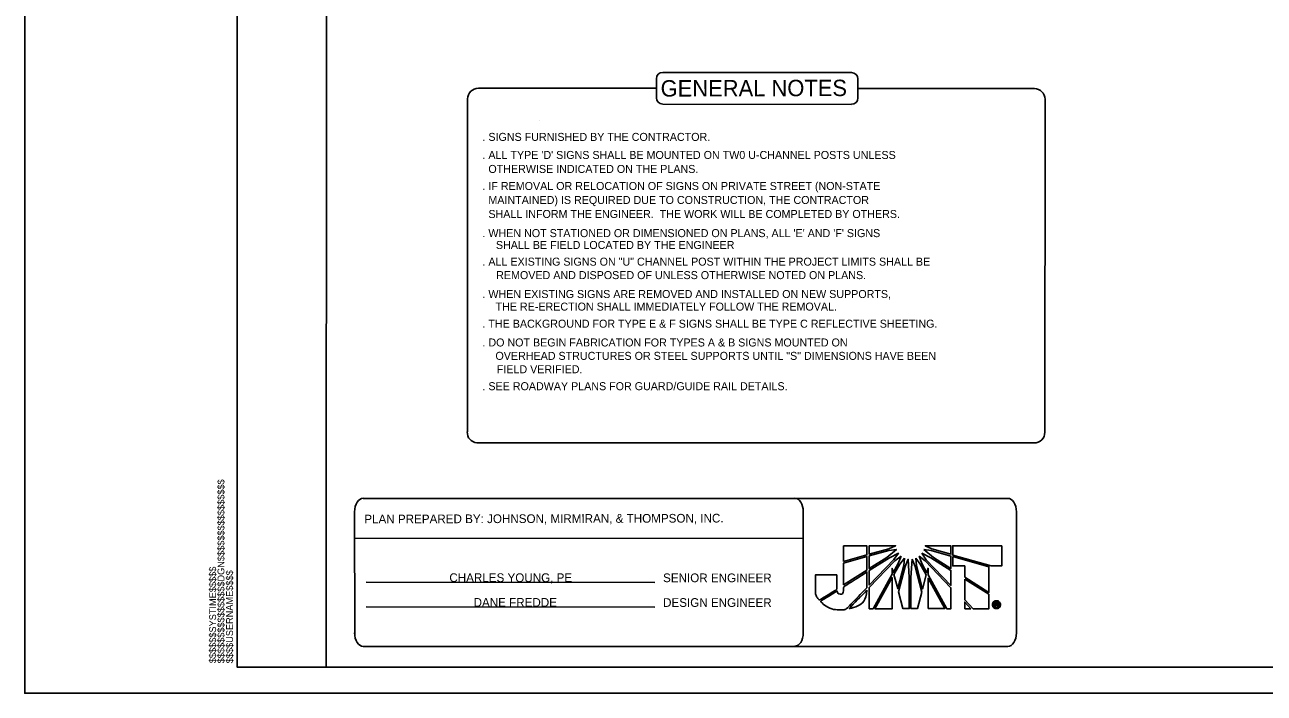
# Model space of a CAD drawing. Extents: x 49201 to 52602, y 49383 to 50479.
# Drawn here: x 50703 to 51649, y 49383 to 49894 of the extents above; entities that cross this region are included whole.
import ezdxf

# ---------------------------------------------------------------- set-up
doc = ezdxf.new("R2010")
doc.units = 0
for name, color, linetype in [('Default', 7, 'Continuous'), ('Old_Level_18', 7, 'Continuous'), ('Old_Level_41', 7, 'Continuous'), ('Old_Level_50', 7, 'Continuous'), ('Sheet Plot Border Outside CELL', 7, 'Continuous'), ('Sheet Title CELL', 7, 'Continuous')]:
    doc.layers.add(name, color=color, linetype=linetype)

msp = doc.modelspace()

# ---------------------------------------------------------------- linework, layer by layer
at = {"layer": 'Default'}
for p, q in [((51095.68, 49820.52), (51095.68, 49820.52)), ((51095.68, 49820.52), (51095.68, 49820.52)), ((50961.32, 49532.17), (51453.54, 49532.17)), ((50954.93, 49428.53), (50954.91, 49521.98)), ((51297.31, 49522.91), (51297.32, 49429.46)), ((51459.95, 49521.93), (51459.95, 49429.37)), ((50954.9, 49501.56), (51297.33, 49501.67)), ((51345.87, 49495.84), (51328.11, 49495.84)), ((51328.11, 49495.84), (51328.11, 49484.05)), ((51345.87, 49488.98), (51345.87, 49495.84)), ((51367.72, 49495.93), (51347.72, 49495.93)), ((51347.72, 49495.93), (51347.72, 49489.56)), ((51362.62, 49493.67), (51367.72, 49495.93)), ((51410.06, 49495.84), (51390.36, 49495.93)), ((51390.36, 49495.93), (51395.34, 49493.58)), ((51410.06, 49489.45), (51410.06, 49495.84)), ((51448.8, 49495.93), (51411.44, 49495.93)), ((51411.44, 49495.93), (51411.44, 49489.07)), ((51448.8, 49480.62), (51448.8, 49495.93)), ((51328.11, 49484.05), (51345.87, 49488.98)), ((51345.87, 49487.69), (51328.11, 49482.7)), ((51345.87, 49477.4), (51345.87, 49487.69)), ((51347.72, 49489.56), (51362.62, 49493.67)), ((51362.62, 49492.29), (51347.72, 49488.19)), ((51347.72, 49488.19), (51347.72, 49478.57)), ((51347.72, 49478.57), (51361.06, 49487.01)), ((51363.12, 49486.81), (51347.72, 49477.01)), ((51361.06, 49487.01), (51368.42, 49493)), ((51368.42, 49493), (51362.62, 49492.29)), ((51369.89, 49490.24), (51363.12, 49486.81)), ((51366.46, 49485.43), (51369.89, 49490.24)), ((51371.94, 49488.1), (51367.22, 49484.46)), ((51369.77, 49482.41), (51371.94, 49488.1)), ((51374.49, 49486.52), (51370.98, 49482)), ((51374, 49481.03), (51374.49, 49486.52)), ((51377.43, 49485.72), (51374.99, 49480.03)), ((51378.19, 49471.71), (51377.43, 49485.72)), ((51380.36, 49485.72), (51379.45, 49471.71)), ((51382.7, 49480.03), (51380.36, 49485.72)), ((51383.2, 49486.52), (51383.79, 49480.83)), ((51386.63, 49482), (51383.2, 49486.52)), ((51385.72, 49488.1), (51387.9, 49482.41)), ((51390.45, 49484.46), (51385.72, 49488.1)), ((51387.81, 49490.24), (51391.24, 49485.34)), ((51394.67, 49486.81), (51387.81, 49490.24)), ((51389.36, 49493), (51396.81, 49486.9)), ((51394.84, 49492.29), (51389.36, 49493)), ((51409.95, 49477.1), (51394.67, 49486.81)), ((51410.06, 49488.1), (51394.84, 49492.29)), ((51395.34, 49493.58), (51410.06, 49489.45)), ((51396.81, 49486.9), (51409.95, 49478.69)), ((51409.95, 49478.69), (51410.06, 49488.1)), ((51411.44, 49489.07), (51411.44, 49488.86)), ((51411.44, 49488.86), (51440.85, 49480.62)), ((51411.44, 49487.81), (51411.44, 49487.69)), ((51438.97, 49479.95), (51411.44, 49487.81)), ((51411.44, 49487.69), (51411.44, 49480.53)), ((51328.11, 49482.7), (51328.11, 49466.14)), ((51328.11, 49466.14), (51345.87, 49477.4)), ((51347.72, 49465.93), (51366.46, 49485.43)), ((51367.22, 49484.46), (51347.72, 49464.05)), ((51347.72, 49477.01), (51347.72, 49465.93)), ((51365.17, 49474.17), (51365.17, 49478.86)), ((51365.17, 49478.86), (51366.05, 49475.64)), ((51366.05, 49475.64), (51369.77, 49482.41)), ((51370.98, 49482), (51366.55, 49473.97)), ((51369.39, 49463.29), (51374, 49481.03)), ((51374.99, 49480.03), (51369.98, 49460.83)), ((51387.81, 49460.54), (51382.7, 49480.03)), ((51383.79, 49480.83), (51388.39, 49462.88)), ((51391.24, 49473.67), (51386.63, 49482)), ((51387.9, 49482.41), (51391.71, 49475.34)), ((51409.95, 49463.88), (51390.45, 49484.46)), ((51391.24, 49485.34), (51409.95, 49465.73)), ((51391.71, 49475.34), (51392.62, 49478.86)), ((51392.62, 49478.86), (51392.62, 49473.67)), ((51409.95, 49465.73), (51409.95, 49477.1)), ((51411.44, 49480.53), (51420.56, 49480.53)), ((51420.56, 49480.53), (51420.56, 49472)), ((51438.98, 49460.33), (51438.97, 49479.95)), ((51440.85, 49480.62), (51448.8, 49480.62)), ((50963.67, 49468.1), (51183.98, 49467.98)), ((51350.66, 49447.93), (51365.17, 49474.17)), ((51365.17, 49471.62), (51352.03, 49447.93)), ((51365.29, 49447.93), (51365.17, 49471.62)), ((51366.55, 49473.97), (51369.39, 49463.29)), ((51378.19, 49448.01), (51378.19, 49471.71)), ((51379.45, 49471.71), (51379.45, 49448.01)), ((51388.39, 49462.88), (51391.24, 49473.67)), ((51392.62, 49473.67), (51406.81, 49447.93)), ((51405.34, 49448.01), (51392.62, 49471.12)), ((51392.62, 49471.12), (51392.62, 49448.01)), ((51420.56, 49472), (51438.98, 49460.33)), ((51420.56, 49470.53), (51420.56, 49454.64)), ((51438.98, 49458.95), (51420.56, 49470.53)), ((51347.72, 49464.05), (51347.72, 49447.93)), ((51369.98, 49460.83), (51373.32, 49448.01)), ((51384.38, 49448.01), (51387.81, 49460.54)), ((51409.95, 49447.93), (51409.95, 49463.88)), ((51438.98, 49447.93), (51438.98, 49458.95)), ((50963.66, 49449.23), (51183.97, 49449.09)), ((51347.72, 49447.93), (51350.66, 49447.93)), ((51352.03, 49447.93), (51365.29, 49447.93)), ((51373.32, 49448.01), (51378.19, 49448.01)), ((51379.45, 49448.01), (51384.38, 49448.01)), ((51392.62, 49448.01), (51405.34, 49448.01)), ((51406.81, 49447.93), (51409.95, 49447.93)), ((51420.56, 49454.64), (51426.92, 49447.93)), ((51425.16, 49447.93), (51420.56, 49452.91)), ((51420.56, 49452.91), (51420.56, 49447.93)), ((51420.56, 49447.93), (51425.16, 49447.93)), ((51426.92, 49447.93), (51438.98, 49447.93)), ((51443.65, 49449.6), (51443.65, 49452.32)), ((51443.65, 49452.32), (51444.77, 49452.32)), ((51444.27, 49449.6), (51443.65, 49449.6)), ((51444.77, 49451.8), (51444.27, 49451.8)), ((51444.27, 49451.8), (51444.27, 49451.16)), ((51444.27, 49451.16), (51444.77, 49451.16)), ((51444.77, 49450.67), (51444.27, 49450.67)), ((51444.27, 49450.67), (51444.27, 49449.6)), ((51444.77, 49453.93), (51444.77, 49453.36)), ((51444.77, 49453.36), (51444.77, 49453.93)), ((51444.77, 49452.32), (51444.77, 49451.8)), ((51444.77, 49451.8), (51444.77, 49452.32)), ((51444.77, 49452.32), (51444.94, 49452.32)), ((51444.84, 49451.8), (51444.77, 49451.8)), ((51444.77, 49451.16), (51444.77, 49450.67)), ((51444.77, 49450.67), (51444.77, 49451.16)), ((51444.77, 49451.16), (51444.79, 49451.16)), ((51444.79, 49450.67), (51444.77, 49450.67)), ((51444.77, 49448.54), (51444.77, 49447.95)), ((51444.77, 49447.95), (51444.77, 49448.54)), ((51444.77, 49448.54), (51444.79, 49448.54)), ((51444.79, 49447.95), (51444.77, 49447.95)), ((51453.53, 49419.13), (50961.32, 49419.12))]:
    msp.add_line(p, q, dxfattribs=at)
for points in [[(51328.11, 49484.05), (51345.87, 49488.98), (51345.87, 49495.84), (51328.11, 49495.84), (51328.11, 49484.05)], [(51362.62, 49493.67), (51367.72, 49495.93), (51347.72, 49495.93), (51347.72, 49489.56), (51362.62, 49493.67)], [(51395.34, 49493.58), (51410.06, 49489.45), (51410.06, 49495.84), (51390.36, 49495.93), (51395.34, 49493.58)], [(51448.8, 49495.93), (51411.44, 49495.93), (51411.44, 49489.07), (51411.44, 49488.86), (51440.85, 49480.62), (51448.8, 49480.62), (51448.8, 49495.93)], [(51328.11, 49466.14), (51345.87, 49477.4), (51345.87, 49487.69), (51328.11, 49482.7), (51328.11, 49466.14)], [(51347.72, 49488.19), (51347.72, 49478.57), (51361.06, 49487.01), (51368.42, 49493), (51362.62, 49492.29), (51347.72, 49488.19)], [(51347.72, 49477.01), (51347.72, 49465.93), (51366.46, 49485.43), (51369.89, 49490.24), (51363.12, 49486.81), (51347.72, 49477.01)], [(51371.94, 49488.1), (51367.22, 49484.46), (51347.72, 49464.05), (51347.72, 49447.93), (51350.66, 49447.93), (51365.17, 49474.17), (51365.17, 49478.86), (51366.05, 49475.64), (51369.77, 49482.41), (51371.94, 49488.1)], [(51374.49, 49486.52), (51370.98, 49482), (51366.55, 49473.97), (51369.39, 49463.29), (51374, 49481.03), (51374.49, 49486.52)], [(51374.99, 49480.03), (51369.98, 49460.83), (51373.32, 49448.01), (51378.19, 49448.01), (51378.19, 49471.71), (51377.43, 49485.72), (51374.99, 49480.03)], [(51380.36, 49485.72), (51379.45, 49471.71), (51379.45, 49448.01), (51384.38, 49448.01), (51387.81, 49460.54), (51382.7, 49480.03), (51380.36, 49485.72)], [(51383.2, 49486.52), (51383.79, 49480.83), (51388.39, 49462.88), (51391.24, 49473.67), (51386.63, 49482), (51383.2, 49486.52)], [(51385.72, 49488.1), (51387.9, 49482.41), (51391.71, 49475.34), (51392.62, 49478.86), (51392.62, 49473.67), (51406.81, 49447.93), (51409.95, 49447.93), (51409.95, 49463.88), (51390.45, 49484.46), (51385.72, 49488.1)], [(51387.81, 49490.24), (51391.24, 49485.34), (51409.95, 49465.73), (51409.95, 49477.1), (51394.67, 49486.81), (51387.81, 49490.24)], [(51389.36, 49493), (51396.81, 49486.9), (51409.95, 49478.69), (51410.06, 49488.1), (51394.84, 49492.29), (51389.36, 49493)], [(51411.44, 49487.81), (51411.44, 49487.69), (51411.44, 49480.53), (51420.56, 49480.53), (51420.56, 49472), (51438.98, 49460.33), (51438.97, 49479.95), (51411.44, 49487.81)], [(51352.03, 49447.93), (51365.29, 49447.93), (51365.17, 49471.62), (51352.03, 49447.93)], [(51392.62, 49448.01), (51405.34, 49448.01), (51392.62, 49471.12), (51392.62, 49448.01)], [(51420.56, 49470.53), (51420.56, 49454.64), (51426.92, 49447.93), (51438.98, 49447.93), (51438.98, 49458.95), (51420.56, 49470.53), (51420.56, 49470.53)], [(51420.56, 49447.93), (51420.56, 49447.93), (51425.16, 49447.93), (51420.56, 49452.91), (51420.56, 49447.93)], [(51444.77, 49452.32), (51443.65, 49452.32), (51443.65, 49449.6), (51444.27, 49449.6), (51444.27, 49450.67), (51444.77, 49450.67), (51444.77, 49451.16), (51444.27, 49451.16), (51444.27, 49451.8), (51444.77, 49451.8), (51444.77, 49452.32)], [(51445.95, 49450.25), (51445.95, 49450.1), (51445.98, 49450), (51445.98, 49449.9), (51446.05, 49449.6), (51445.48, 49449.6)]]:
    msp.add_lwpolyline(points, dxfattribs=at)
for centre, major_axis, start_param, end_param in [((50961.33, 49521.98), (0.01, 10.24), 0.000702, 1.571498), ((51290.91, 49522.02), (0.01, 10.24), 4.713091, 6.283887), ((51453.54, 49521.93), (0.01, 10.24), 4.713091, 6.283887), ((50961.32, 49429.41), (-0.01, -10.24), 4.713091, 6.283887), ((51290.91, 49429.46), (-0.01, -10.24), 0.000702, 1.571498), ((51453.53, 49429.37), (-0.01, -10.24), 0.000702, 1.571498)]:
    msp.add_ellipse(centre, major_axis=major_axis, ratio=0.62659, start_param=start_param, end_param=end_param, dxfattribs=at)
for points, degree in [([(51323, 49473.76), (51323, 49473.76), (51306.55, 49473.76), (51306.55, 49473.76), (51306.55, 49473.76), (51306.55, 49463.47), (51306.55, 49463.47), (51306.55, 49463.47), (51306.55, 49462.38), (51306.55, 49462.38), (51306.55, 49459.16), (51307.61, 49456.61), (51309.49, 49454.46), (51309.49, 49454.46), (51323, 49462.68), (51323, 49462.88), (51323, 49462.88), (51323, 49473.76), (51323, 49473.76)], 3), ([(51323, 49473.76), (51323, 49473.76), (51306.55, 49473.76), (51306.55, 49473.76), (51306.55, 49473.76), (51306.55, 49463.47), (51306.55, 49463.47), (51306.55, 49463.47), (51306.55, 49462.38), (51306.55, 49462.38), (51306.55, 49459.16), (51307.61, 49456.61), (51309.49, 49454.46), (51309.49, 49454.46), (51323, 49462.68), (51323, 49462.88), (51323, 49462.88), (51323, 49473.76), (51323, 49473.76)], 3), ([(51325.55, 49458.95), (51324.5, 49458.95), (51323.59, 49459.54), (51323.21, 49461.5), (51323.21, 49461.5), (51310.45, 49453.61), (51310.45, 49453.61), (51314.38, 49449.48), (51320.66, 49447.02), (51325.97, 49447.02), (51327.34, 49447.02), (51328.4, 49447.13), (51329.86, 49447.43), (51329.86, 49447.43), (51345.88, 49463.97), (51345.88, 49463.97), (51345.88, 49463.97), (51345.87, 49475.93), (51345.87, 49475.93), (51345.87, 49475.93), (51328.11, 49464.64), (51328.11, 49464.64), (51328.11, 49460.15), (51327.02, 49458.95), (51325.55, 49458.95)], 3), ([(51325.55, 49458.95), (51324.5, 49458.95), (51323.59, 49459.54), (51323.21, 49461.5), (51323.21, 49461.5), (51310.45, 49453.61), (51310.45, 49453.61), (51314.38, 49449.48), (51320.66, 49447.02), (51325.97, 49447.02), (51327.34, 49447.02), (51328.4, 49447.13), (51329.86, 49447.43), (51329.86, 49447.43), (51345.88, 49463.97), (51345.88, 49463.97), (51345.88, 49463.97), (51345.87, 49475.93), (51345.87, 49475.93), (51345.87, 49475.93), (51328.11, 49464.64), (51328.11, 49464.64), (51328.11, 49460.15), (51327.02, 49458.95), (51325.55, 49458.95)], 3), ([(51345.88, 49462.09), (51345.88, 49462.09), (51332.03, 49447.81), (51332.03, 49447.81), (51338.81, 49449.48), (51345.55, 49453.97), (51345.88, 49462.09)], 3), ([(51345.88, 49462.09), (51345.88, 49462.09), (51332.03, 49447.81), (51332.03, 49447.81), (51338.81, 49449.48), (51345.55, 49453.97), (51345.88, 49462.09)], 3), ([(51444.77, 49447.95), (51443.95, 49447.95), (51443.23, 49448.25), (51442.64, 49448.84), (51442.05, 49449.41), (51441.75, 49450.12), (51441.75, 49450.96), (51441.75, 49451.8), (51442.05, 49452.52), (51442.64, 49453.06), (51443.23, 49453.63), (51443.93, 49453.93), (51444.77, 49453.93), (51444.77, 49453.93), (51444.77, 49453.36), (51444.77, 49453.36), (51444.1, 49453.36), (51443.53, 49453.14), (51443.06, 49452.69), (51442.59, 49452.22), (51442.35, 49451.63), (51442.35, 49450.96), (51442.35, 49450.3), (51442.59, 49449.7), (51443.06, 49449.23), (51443.53, 49448.76), (51444.1, 49448.54), (51444.77, 49448.54), (51444.77, 49448.54), (51444.77, 49447.95), (51444.77, 49447.95), (51444.77, 49447.95), (51444.77, 49447.95), (51444.77, 49447.95)], 3), ([(51444.77, 49447.95), (51443.95, 49447.95), (51443.23, 49448.25), (51442.64, 49448.84), (51442.05, 49449.41), (51441.75, 49450.12), (51441.75, 49450.96), (51441.75, 49451.8), (51442.05, 49452.52), (51442.64, 49453.06), (51443.23, 49453.63), (51443.93, 49453.93), (51444.77, 49453.93)], 3), ([(51444.77, 49453.36), (51444.1, 49453.36), (51443.53, 49453.14), (51443.06, 49452.69), (51442.59, 49452.22), (51442.35, 49451.63), (51442.35, 49450.96), (51442.35, 49450.3), (51442.59, 49449.7), (51443.06, 49449.23), (51443.53, 49448.76), (51444.1, 49448.54), (51444.77, 49448.54)], 3), ([(51447.8, 49450.96), (51447.8, 49450.12), (51447.51, 49449.41), (51446.94, 49448.81), (51446.35, 49448.25), (51445.63, 49447.95), (51444.79, 49447.95), (51444.79, 49447.95), (51444.79, 49447.95), (51444.77, 49447.95), (51444.77, 49447.95), (51444.77, 49448.54), (51444.77, 49448.54), (51444.79, 49448.54), (51444.79, 49448.54), (51444.79, 49448.54), (51445.46, 49448.54), (51446.03, 49448.76), (51446.49, 49449.23), (51446.96, 49449.7), (51447.21, 49450.3), (51447.21, 49450.96), (51447.21, 49451.63), (51446.96, 49452.22), (51446.49, 49452.69), (51446.03, 49453.14), (51445.46, 49453.36), (51444.77, 49453.36), (51444.77, 49453.36), (51444.77, 49453.93), (51444.77, 49453.93), (51445.61, 49453.93), (51446.32, 49453.63), (51446.91, 49453.06), (51447.51, 49452.52), (51447.8, 49451.8), (51447.8, 49450.96), (51447.8, 49450.96), (51447.8, 49450.96), (51447.8, 49450.96)], 3), ([(51444.77, 49453.93), (51445.61, 49453.93), (51446.32, 49453.63), (51446.91, 49453.06), (51447.51, 49452.52), (51447.8, 49451.8), (51447.8, 49450.96)], 3), ([(51444.79, 49448.54), (51445.46, 49448.54), (51446.03, 49448.76), (51446.49, 49449.23), (51446.96, 49449.7), (51447.21, 49450.3), (51447.21, 49450.96), (51447.21, 49451.63), (51446.96, 49452.22), (51446.49, 49452.69), (51446.03, 49453.14), (51445.46, 49453.36), (51444.77, 49453.36)], 3), ([(51444.77, 49450.67), (51444.77, 49450.67), (51444.77, 49451.16), (51444.77, 49451.16), (51444.77, 49451.16), (51444.79, 49451.16), (51444.79, 49451.16), (51445.19, 49451.16), (51445.38, 49451.28), (51445.38, 49451.51), (51445.38, 49451.7), (51445.21, 49451.8), (51444.84, 49451.8), (51444.84, 49451.8), (51444.77, 49451.8), (51444.77, 49451.8), (51444.77, 49451.8), (51444.77, 49452.32), (51444.77, 49452.32), (51444.77, 49452.32), (51444.94, 49452.32), (51444.94, 49452.32), (51445.63, 49452.32), (51445.98, 49452.05), (51445.98, 49451.51), (51445.98, 49451.26), (51445.88, 49451.06), (51445.65, 49450.91), (51445.83, 49450.81), (51445.93, 49450.59), (51445.95, 49450.25), (51445.95, 49450.25), (51445.95, 49450.1), (51445.95, 49450.1), (51445.95, 49450.1), (51445.98, 49450), (51445.98, 49450), (51445.98, 49450), (51445.98, 49449.9), (51445.98, 49449.9), (51445.98, 49449.9), (51446.05, 49449.6), (51446.05, 49449.6), (51446.05, 49449.6), (51445.48, 49449.6), (51445.48, 49449.6), (51445.41, 49449.75), (51445.36, 49449.9), (51445.36, 49450.1), (51445.36, 49450.35), (51445.33, 49450.49), (51445.26, 49450.57), (51445.19, 49450.62), (51445.04, 49450.67), (51444.79, 49450.67), (51444.79, 49450.67), (51444.77, 49450.67), (51444.77, 49450.67)], 3), ([(51444.79, 49451.16), (51445.19, 49451.16), (51445.38, 49451.28), (51445.38, 49451.51), (51445.38, 49451.7), (51445.21, 49451.8), (51444.84, 49451.8)], 3), ([(51447.8, 49450.96), (51447.8, 49450.12), (51447.51, 49449.41), (51446.94, 49448.81), (51446.35, 49448.25), (51445.63, 49447.95), (51444.79, 49447.95)], 3), ([(51445.26, 49450.57), (51445.19, 49450.62), (51445.04, 49450.67), (51444.79, 49450.67)], 2), ([(51444.94, 49452.32), (51445.63, 49452.32), (51445.98, 49452.05), (51445.98, 49451.51), (51445.98, 49451.26), (51445.88, 49451.06), (51445.65, 49450.91)], 3), ([(51445.48, 49449.6), (51445.41, 49449.75), (51445.36, 49449.9), (51445.36, 49450.1), (51445.36, 49450.35), (51445.33, 49450.49), (51445.26, 49450.57)], 3), ([(51445.65, 49450.91), (51445.83, 49450.81), (51445.93, 49450.59), (51445.95, 49450.25)], 2)]:
    msp.add_open_spline(points, degree=degree, dxfattribs=at)
at = {"layer": 'Old_Level_18'}
msp.add_lwpolyline([(52365.34, 50453.17), (50865.34, 50453.17), (50865.34, 49403.17), (52365.34, 49403.17)], close=True, dxfattribs=at)
at = {"layer": 'Old_Level_50'}
msp.add_line((50703.13, 49383.36), (50703.13, 49383.36), dxfattribs=at)
at = {"layer": 'Sheet Plot Border Outside CELL'}
msp.add_lwpolyline([(52386.04, 50479.27), (50703.13, 50479.27), (50703.13, 49383.36), (52386.04, 49383.36)], close=True, dxfattribs=at)
at = {"layer": 'Sheet Title CELL'}
for p, q in [((51049.32, 49845.44), (51185.2, 49845.38)), ((51185.2, 49838.17), (51185.2, 49852.63)), ((51339.01, 49838.02), (51339.02, 49852.48)), ((51339.02, 49845.24), (51473.74, 49845.18)), ((51040.92, 49582.9), (51041.12, 49837.25)), ((51481.73, 49582.7), (51481.93, 49836.97)), ((51048.05, 49574.7), (51473.53, 49574.5))]:
    msp.add_line(p, q, dxfattribs=at)
for points in [[(50933.09, 49403.17), (50933.65, 50453.17)], [(51190.13, 49857.54), (51334.1, 49857.4)], [(51190.12, 49833.24), (51334.09, 49833.1)]]:
    msp.add_lwpolyline(points, dxfattribs=at)
for centre, radius, start, end in [((51190.12, 49852.62), 4.92, 89.97341, 179.97341), ((51334.1, 49852.48), 4.92, 359.97341, 89.97341), ((51049.32, 49837.24), 8.2, 89.97341, 179.97341), ((51473.73, 49836.98), 8.2, 359.97341, 89.97341), ((51190.12, 49838.16), 4.92, 179.97341, 269.97341), ((51334.09, 49838.03), 4.92, 269.97341, 359.97341), ((51048.58, 49582.37), 7.69, 175.99958, 265.99958), ((51473.53, 49582.7), 8.2, 269.97341, 359.97341)]:
    msp.add_arc(centre, radius, start, end, dxfattribs=at)

# ---------------------------------------------------------------- texts
at = {"layer": 'Default'}
for s, height, rotation, p in [('GENERAL NOTES', 12.5119, 0.15565, (51188.46, 49839.03)), ('PLAN PREPARED BY: JOHNSON, MIRMIRAN, & THOMPSON, INC.', 6.6381, 0.14965, (50962.28, 49513.04)), ('CHARLES YOUNG, PE', 6.6381, 359.9674, (51027.19, 49468.31)), ('SENIOR ENGINEER', 6.6381, 359.9674, (51190.32, 49468.18)), ('DANE FREDDE', 6.6381, 359.9674, (51045.68, 49449.44)), ('DESIGN ENGINEER', 6.6381, 359.9674, (51190.31, 49449.32))]:
    msp.add_text(s, height=height, rotation=rotation, dxfattribs=at).set_placement(p)
for s, p in [('. SIGNS FURNISHED BY THE CONTRACTOR.', (51052.45, 49805.18)), (". ALL TYPE 'D' SIGNS SHALL BE MOUNTED ON TW0 U-CHANNEL POSTS UNLESS", (51052.45, 49791.4)), ('  OTHERWISE INDICATED ON THE PLANS.', (51052.45, 49780.71)), ('. IF REMOVAL OR RELOCATION OF SIGNS ON PRIVATE STREET (NON-STATE ', (51052.45, 49767.7)), ('  MAINTAINED) IS REQUIRED DUE TO CONSTRUCTION, THE CONTRACTOR ', (51052.45, 49757.01)), ('  SHALL INFORM THE ENGINEER.  THE WORK WILL BE COMPLETED BY OTHERS.', (51052.45, 49746.32)), (". WHEN NOT STATIONED OR DIMENSIONED ON PLANS, ALL 'E' AND 'F' SIGNS ", (51052.45, 49731.7)), ('SHALL BE FIELD LOCATED BY THE ENGINEER', (51062.73, 49722.64)), ('. ALL EXISTING SIGNS ON "U" CHANNEL POST WITHIN THE PROJECT LIMITS SHALL BE', (51052.45, 49709.91)), ('REMOVED AND DISPOSED OF UNLESS OTHERWISE NOTED ON PLANS.', (51062.93, 49699.63)), ('. WHEN EXISTING SIGNS ARE REMOVED AND INSTALLED ON NEW SUPPORTS, ', (51052.45, 49685.18)), ('THE RE-ERECTION SHALL IMMEDIATELY FOLLOW THE REMOVAL.', (51062.45, 49675.58)), ('. THE BACKGROUND FOR TYPE E & F SIGNS SHALL BE TYPE C REFLECTIVE SHEETING. ', (51052.45, 49662.52)), ('. DO NOT BEGIN FABRICATION FOR TYPES A & B SIGNS MOUNTED ON ', (51052.45, 49648.18)), ('OVERHEAD STRUCTURES OR STEEL SUPPORTS UNTIL "S" DIMENSIONS HAVE BEEN', (51062.38, 49637.96)), ('FIELD VERIFIED.', (51063.42, 49627.74)), ('. SEE ROADWAY PLANS FOR GUARD/GUIDE RAIL DETAILS.', (51052.45, 49614.79))]:
    msp.add_text(s, height=6.1096, dxfattribs=at).set_placement(p)
at = {"layer": 'Old_Level_41'}
for s, p in [('$$$$$$$$$$$$$$$$DGN$$$$$$$$$$$$$$$$', (50855.49, 49406.17)), ('$$$$$$SYSTIME$$$$$', (50849.14, 49406.27)), ('$$$$USERNAME$$$$', (50862.04, 49406.22))]:
    msp.add_text(s, height=5.25, rotation=89.99999, dxfattribs=at).set_placement(p)

doc.saveas('drawing.dxf')
